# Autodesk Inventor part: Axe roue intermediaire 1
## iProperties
Author: Flavien MARTY
Shininess: 60.0
PropertySet Name: _Private Model Information
Created: 2001-10
Part Number: Axe roue intermediaire 1
Material: Par défaut
Document SubType Name: Modélisation
Designer: Flavien MARTY
Control State: 0
Master: False
Checked Out: False
PropertySet Name: Design Tracking Control
Density: 0.0
Volumn: 0.0
Area: 0.0
PropertySet Name: Model Information
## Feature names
1. Base1
